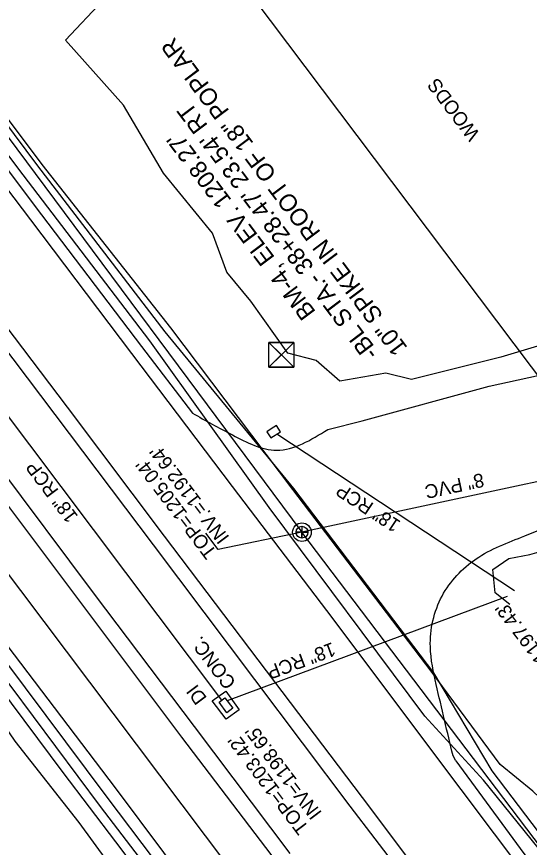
# Model space of a CAD drawing. Extents: x 1262092 to 1264624, y 774970 to 778314.
# Drawn here: x 1262454.7 to 1262603.1, y 777671.7 to 777912.2 of the extents above; entities that cross this region are included whole.
import ezdxf

# ---------------------------------------------------------------- set-up
doc = ezdxf.new("R2010")
doc.units = 0
for name, color, linetype in [('CTL Vertical Benchmark CELL', 7, 'Continuous'), ('Exist Horizontal Alignment', 7, 'Continuous'), ('Exist Right of Way Line', 7, 'Continuous'), ('Exist Roads EOP', 7, 'Continuous'), ('Exist Roads EOP Other', 7, 'Continuous'), ('Exist Roads EOT', 7, 'Continuous'), ('Exist Structure Minor Drop Inlet', 7, 'Continuous'), ('Exist Structure Minor Drop Inlet Text', 7, 'Continuous'), ('Exist Structure Minor Drop Inlet Top Elevation', 7, 'Continuous'), ('Exist Structure Minor Paved Ditch or Gutter', 7, 'Continuous'), ('Exist Structure Minor Paved Ditch or Gutter Text', 7, 'Continuous'), ('Exist Structure Minor Pipes RCP 18 Inch', 7, 'Continuous'), ('Exist Structure Minor Pipes RCP 18 Inch Invert', 7, 'Continuous'), ('Exist Structure Minor Pipes RCP 18 Inch Text', 7, 'Continuous'), ('Exist Utilities Gas UG Line SUE LOS B', 7, 'Continuous'), ('Exist Utilities Sanitary Sewer Manhole CELL', 7, 'Continuous'), ('Exist Utilities Sanitary Sewer Manhole Leader', 7, 'Continuous'), ('Exist Utilities Sanitary Sewer Manhole Text', 7, 'Continuous'), ('Exist Utilities Sanitary Sewer UG Line', 7, 'Continuous'), ('Exist Utilities Sanitary Sewer UG Line Text', 7, 'Continuous'), ('Exist Utilities Telephone UG FO SUE LOS B', 7, 'Continuous'), ('Exist Utilities Water UG Line SUE LOS B', 7, 'Continuous'), ('Exist Vegetation Woods Line Text', 7, 'Continuous'), ('Prop Conc 5in Monolithic Keyed In Island', 7, 'Continuous'), ('Prop Terminator CELL', 7, 'Continuous'), ('Typical Text Label CELL', 7, 'Continuous')]:
    doc.layers.add(name, color=color, linetype=linetype)

# ---------------------------------------------------------------- blocks, each defined once
blk = doc.blocks.new('CTL VERTICAL BENCHMARK')
at = {"layer": 'CTL Vertical Benchmark CELL'}
blk.add_line((0, 0), (0, 0), dxfattribs=at)
blk.add_lwpolyline([(-0.072, 0.07175), (0.07175, 0.07175), (0.07175, -0.072), (-0.072, -0.072)], close=True, dxfattribs=at)
for points in [[(0.07175, 0.07175), (-0.072, -0.072), (-0.000125, -0.000125), (0.07175, -0.072), (-0.072, 0.07175)], [(-0.000125, -0.000125), (0.07175, 0.07175), (-0.072, 0.07175), (-0.000125, -0.000125)], [(-0.000125, -0.000125), (-0.072, -0.072), (0.07175, -0.072), (-0.000125, -0.000125)]]:
    blk.add_lwpolyline(points, dxfattribs=at)
blk = doc.blocks.new('EXIST UTILITIES SANITARY SEWER MANHOLE')
at = {"layer": 'Exist Utilities Sanitary Sewer Manhole CELL'}
blk.add_lwpolyline([(0, 0.03425), (0, -0.03425), (0, 0), (0.03425, 0), (-0.03425, 0)], dxfattribs=at)
for radius in [0.05389, 0.03425]:
    blk.add_circle((0, 0), radius, dxfattribs=at)

msp = doc.modelspace()

# ---------------------------------------------------------------- linework, layer by layer
at = {"layer": 'Exist Horizontal Alignment'}
msp.add_line((1264460.35, 775084.79), (1262255.05, 778012.66), dxfattribs=at)
at = {"layer": 'Exist Right of Way Line'}
msp.add_line((1262380.46, 778107.12), (1263428.45, 776715.75), dxfattribs=at)
at = {"layer": 'Exist Roads EOP'}
for p, q in [((1262601.79, 777761.82), (1262629.33, 777772.97)), ((1262581.77, 777696.76), (1262581, 777698.2))]:
    msp.add_line(p, q, dxfattribs=at)
for points in [[(1262311.57, 778054.09), (1262320.31, 778042.27), (1262347.65, 778006.04), (1262376.01, 777968.97), (1262404.37, 777930.89), (1262432.91, 777893.24), (1262461.84, 777854.83), (1262490.86, 777816.65), (1262505.6, 777797.35)], [(1262285.77, 778035.09), (1262294.3, 778023.82), (1262322.73, 777986.32), (1262351.06, 777948.49), (1262379.86, 777910.83), (1262408.98, 777872.17), (1262437.51, 777834.34), (1262465.79, 777796.98), (1262494.21, 777759.25), (1262523.56, 777720.28), (1262551.17, 777683.56), (1262580.06, 777645.73)], [(1262533.86, 777669.85), (1262506.16, 777706.68), (1262477.25, 777744.96), (1262448.83, 777782.76), (1262448.77, 777782.75), (1262419.94, 777820.99), (1262391.44, 777858.59), (1262362.67, 777897.37), (1262333.74, 777935.31), (1262305.02, 777973.3), (1262276.84, 778010.82), (1262268.09, 778022.33)], [(1262508.59, 777649.5), (1262480.62, 777686.61), (1262451.55, 777725.45), (1262423.03, 777763.23), (1262394.37, 777801.14), (1262366.02, 777838.6), (1262337.3, 777876.52), (1262308.59, 777914.31), (1262279.57, 777952.95), (1262251.16, 777991.02), (1262242.02, 778002.99)], [(1262581.77, 777696.76), (1262605.02, 777665.12), (1262633.36, 777627.24), (1262661.91, 777589.34), (1262690.46, 777551.49), (1262719.22, 777513.4), (1262746.97, 777476.08), (1262773.62, 777440.76), (1262802.75, 777402.21), (1262831.32, 777364.09), (1262858.19, 777328.14), (1262886.09, 777290.94), (1262913.38, 777255.47), (1262941.92, 777217.23), (1262974.58, 777174.56)]]:
    msp.add_lwpolyline(points, dxfattribs=at)
for points in [[(1262505.6, 777797.35), (1262517.14, 777791.06), (1262529.95, 777786.65), (1262544.75, 777792.63)], [(1262581, 777698.2), (1262576.15, 777718.84), (1262574.44, 777729.73), (1262577.84, 777744.43), (1262587.67, 777755.18), (1262601.79, 777761.82)]]:
    msp.add_spline(points, degree=3, dxfattribs=at)
at = {"layer": 'Exist Roads EOP Other'}
msp.add_lwpolyline([(1262544.75, 777792.63), (1262554.66, 777795.19), (1262591.5, 777805.2), (1262611.36, 777809.52), (1262633.47, 777814.22), (1262657.91, 777819.26), (1262661.57, 777820.89), (1262663.59, 777822.69), (1262664.84, 777824.45), (1262667.34, 777828.67), (1262677.77, 777830.58)], dxfattribs=at)
at = {"layer": 'Exist Roads EOT'}
for points in [[(1262308.34, 778051.79), (1262317.32, 778039.93), (1262344.37, 778004.19), (1262372.89, 777966.62), (1262401.21, 777929.2), (1262429.93, 777891.21), (1262458.73, 777853.38), (1262487.94, 777814.62), (1262517.12, 777776.18), (1262546.22, 777737.8), (1262573.92, 777700.82), (1262602.3, 777663.12)], [(1262289.2, 778037.57), (1262297.52, 778026.31), (1262325.76, 777988.99), (1262354.59, 777951.12), (1262382.95, 777913.24), (1262412.22, 777874.41), (1262440.97, 777836.5), (1262469.27, 777799.15), (1262497.42, 777761.79), (1262526.95, 777722.8), (1262554.72, 777686.15), (1262583.3, 777648.11)], [(1262530.21, 777667.14), (1262502.53, 777703.54), (1262473.57, 777742.17), (1262445.07, 777779.99), (1262416.17, 777818.02), (1262387.95, 777855.59), (1262358.59, 777894.64), (1262330.16, 777932.09), (1262301.01, 777970.53), (1262273.04, 778007.62), (1262264.28, 778019.28)], [(1262511.28, 777651.42), (1262483.32, 777688.89), (1262454.05, 777727.36), (1262425.45, 777765.13), (1262396.78, 777803.08), (1262368.42, 777840.5), (1262339.71, 777878.55), (1262311.54, 777915.71), (1262282.01, 777954.91), (1262253.58, 777992.51), (1262244.27, 778004.78)]]:
    msp.add_lwpolyline(points, dxfattribs=at)
at = {"layer": 'Exist Structure Minor Drop Inlet'}
msp.add_lwpolyline([(1262529.87, 777793.77), (1262528.4, 777792.85), (1262527.1, 777792.02), (1262528.25, 777790.2), (1262531.02, 777791.95)], close=True, dxfattribs=at)
msp.add_lwpolyline([(1262514.97, 777714.99), (1262517.24, 777711.96), (1262515.53, 777710.65), (1262513.32, 777713.68), (1262514.97, 777714.99)], dxfattribs=at)
at = {"layer": 'Exist Structure Minor Paved Ditch or Gutter'}
msp.add_lwpolyline([(1262511.3, 777714.1), (1262515.24, 777716.92), (1262519.07, 777711.51), (1262515.32, 777708.77), (1262511.3, 777714.1)], dxfattribs=at)
at = {"layer": 'Exist Structure Minor Pipes RCP 18 Inch'}
for p, q in [((1262514.1, 777714.3), (1262275, 778031.81)), ((1262529.98, 777791.39), (1262598.81, 777746.05)), ((1262596.69, 777744.27), (1262515.67, 777714.06))]:
    msp.add_line(p, q, dxfattribs=at)
at = {"layer": 'Exist Utilities Gas UG Line SUE LOS B'}
msp.add_lwpolyline([(1262994.39, 777166.73), (1262980.63, 777180.77), (1262951.12, 777219.34), (1262915.77, 777266.99), (1262883.3, 777310), (1262857.54, 777344.34), (1262828.14, 777381.91), (1262793.47, 777427.19), (1262760.54, 777472.85), (1262727.33, 777519.3), (1262694.08, 777555.83), (1262655.09, 777608.15), (1262623.1, 777653.3), (1262592.34, 777693.87), (1262575.48, 777722.21), (1262534.9, 777775.61), (1262497.72, 777820.92), (1262460.79, 777868.95), (1262430.33, 777909.82), (1262335.35, 778033.97), (1262366.66, 777994.16), (1262337.19, 778032.97), (1262314.26, 778062.88)], dxfattribs=at)
msp.add_lwpolyline([(1262994.39, 777166.73), (1262980.63, 777180.77), (1262951.12, 777219.34), (1262915.77, 777266.99), (1262883.3, 777310), (1262857.54, 777344.34), (1262828.14, 777381.91), (1262793.47, 777427.19), (1262760.54, 777472.85), (1262727.33, 777519.3), (1262694.08, 777555.83), (1262655.09, 777608.15), (1262623.1, 777653.3), (1262592.34, 777693.87), (1262575.48, 777722.21), (1262534.9, 777775.61), (1262497.72, 777820.92), (1262460.79, 777868.95), (1262430.33, 777909.82), (1262335.35, 778033.97), (1262366.66, 777994.16), (1262337.19, 778032.97), (1262314.26, 778062.88)], dxfattribs=at)
at = {"layer": 'Exist Utilities Sanitary Sewer Manhole Leader'}
msp.add_lwpolyline([(1262537.27, 777762.91), (1262513.03, 777757.87), (1262509.43, 777762.66)], dxfattribs=at)
at = {"layer": 'Exist Utilities Sanitary Sewer UG Line'}
for p in [(1262150.97, 778282.31), (1263142.14, 776964.69)]:
    msp.add_line(p, (1262537.27, 777762.91), dxfattribs=at)
msp.add_lwpolyline([(1262668.77, 777791.06), (1262537.27, 777762.91)], dxfattribs=at)
at = {"layer": 'Exist Utilities Telephone UG FO SUE LOS B'}
for points in [[(1262989.94, 777168.07), (1262951.99, 777219.94), (1262916.42, 777267.81), (1262888.77, 777316.31), (1262864.92, 777351.47), (1262838.91, 777387.68), (1262799.61, 777432.02), (1262765.27, 777476.73), (1262731.32, 777522.28), (1262700.44, 777560.94), (1262661.97, 777612.3), (1262627.92, 777657.64), (1262612.11, 777680.33), (1262604.08, 777687.9), (1262594.67, 777695.7), (1262574.71, 777722.66), (1262534.65, 777775.25), (1262499.34, 777822.06), (1262462.07, 777869.42), (1262431.13, 777910.63), (1262336.58, 778034.92), (1262368.35, 777994.88), (1262338.32, 778033.37), (1262315.72, 778063.86)], [(1262989.94, 777168.07), (1262951.99, 777219.94), (1262916.42, 777267.81), (1262888.77, 777316.31), (1262864.92, 777351.47), (1262838.91, 777387.68), (1262799.61, 777432.02), (1262765.27, 777476.73), (1262731.32, 777522.28), (1262700.44, 777560.94), (1262661.97, 777612.3), (1262627.92, 777657.64), (1262612.11, 777680.33), (1262604.08, 777687.9), (1262594.67, 777695.7), (1262574.71, 777722.66), (1262534.65, 777775.25), (1262499.34, 777822.06), (1262462.07, 777869.42), (1262431.13, 777910.63), (1262336.58, 778034.92), (1262368.35, 777994.88), (1262338.32, 778033.37), (1262315.72, 778063.86)], [(1262982.78, 777167.11), (1262946.46, 777216.4), (1262911.63, 777263.89), (1262904.55, 777273.66), (1262904.75, 777279.08), (1262882.68, 777309.56), (1262855.72, 777342.59), (1262826.17, 777380.64), (1262792.14, 777426.47), (1262758.72, 777471.04), (1262724.36, 777517.1), (1262692.7, 777554.83), (1262654.13, 777607.32), (1262621.89, 777651.43), (1262589.79, 777691.14), (1262572.86, 777709.66), (1262527.82, 777770.05), (1262493.25, 777818.33), (1262456.6, 777866.38), (1262426.24, 777906.46), (1262391.81, 777952.18), (1262362.73, 777991.03), (1262332.92, 778030.12), (1262309.95, 778059.98)], [(1262497.69, 777644.72), (1262472.81, 777678.82), (1262454.22, 777702.45), (1262410.39, 777767.02), (1262381.85, 777803.45), (1262346.33, 777843.25), (1262319.52, 777872.83), (1262288.46, 777910.54), (1262263.91, 777943.64), (1262260.24, 777952.77), (1262251.56, 777965.81), (1262224.91, 778006.43)]]:
    msp.add_lwpolyline(points, dxfattribs=at)
at = {"layer": 'Exist Utilities Water UG Line SUE LOS B'}
msp.add_lwpolyline([(1262961.53, 777041.32), (1262916.91, 777099.45), (1262892.75, 777131.3), (1262862.6, 777171.1), (1262817.98, 777226.85), (1262789.55, 777268.74), (1262774.27, 777287.66), (1262763.83, 777305.05), (1262732.33, 777346.94), (1262685.88, 777410.11), (1262660.87, 777443.18), (1262632.31, 777481.08), (1262598.3, 777526.4), (1262560.14, 777576.52), (1262506.51, 777647.45), (1262479.01, 777683.48), (1262453.07, 777718.25), (1262416.94, 777766.02), (1262382.77, 777811.78), (1262358.61, 777844.73), (1262327.38, 777885.68), (1262302.32, 777918.54), (1262259.45, 777971.43), (1262223.66, 778020.3)], dxfattribs=at)
at = {"layer": 'Prop Conc 5in Monolithic Keyed In Island'}
for points in [[(1262533.14, 777814.74), (1262522.5, 777829.79), (1262515.5, 777838.16), (1262511.37, 777849.45), (1262497.15, 777866.82), (1262485.63, 777886.53), (1262468.79, 777905.4), (1262479.72, 777917.06), (1262479.8, 777939.53), (1262486.53, 777963.05), (1262485.45, 777968.26)], [(1262669.52, 777841.52), (1262663.48, 777834.07), (1262654.46, 777829.52), (1262625.06, 777822.67), (1262594.86, 777813.61), (1262568.96, 777807.09), (1262561.51, 777808.92), (1262548.24, 777806.67), (1262541.36, 777812.67), (1262533.14, 777814.74)], [(1262597.47, 777741.98), (1262593.25, 777745.35), (1262592.49, 777752.09), (1262597.12, 777755.26), (1262603.2, 777756.41), (1262615.39, 777759.97), (1262624.68, 777755.85), (1262626.75, 777749.85), (1262631.1, 777744.24), (1262642.14, 777734.31), (1262649.45, 777730.68), (1262655.3, 777732.37), (1262661.91, 777740.44), (1262669.23, 777746.99), (1262676.7, 777747.14), (1262684.82, 777742.44), (1262695.74, 777744.15), (1262709.96, 777741.06), (1262732.77, 777726.31), (1262741.03, 777722.96), (1262742.69, 777718.79), (1262747.97, 777708.45), (1262760.99, 777691.69), (1262778.66, 777667.76)]]:
    msp.add_lwpolyline(points, dxfattribs=at)
at = {"layer": 'Typical Text Label CELL'}
msp.add_lwpolyline([(1262768.2, 777292.26), (1262757.43, 777308.58), (1262750.97, 777317.87), (1262727.73, 777348.88), (1262712, 777369.55), (1262697.36, 777389.13), (1262675.04, 777418.88), (1262656.25, 777443.92), (1262630.05, 777478.82), (1262611.34, 777503.87), (1262588.61, 777533.8), (1262569.91, 777558.5), (1262554.82, 777578.68), (1262539.79, 777598.72), (1262516.99, 777628.51), (1262502.14, 777648.38), (1262483.36, 777673.29), (1262468.18, 777693.3), (1262449.46, 777718.32)], dxfattribs=at)

# ---------------------------------------------------------------- block references
at = {"layer": 'CTL Vertical Benchmark CELL', "xscale": 50, "yscale": 50}
msp.add_blockref('CTL VERTICAL BENCHMARK', (1262531.33, 777814.27), dxfattribs=at)
msp.add_blockref('CTL VERTICAL BENCHMARK', (1262531.33, 777814.27), dxfattribs=at)
msp.add_blockref('CTL VERTICAL BENCHMARK', (1262531.33, 777814.27), dxfattribs=at)
at = {"layer": 'Exist Utilities Sanitary Sewer Manhole CELL', "xscale": 50, "yscale": 50}
msp.add_blockref('EXIST UTILITIES SANITARY SEWER MANHOLE', (1262537.27, 777762.91), dxfattribs=at)
msp.add_blockref('EXIST UTILITIES SANITARY SEWER MANHOLE', (1262537.27, 777762.91), dxfattribs=at)

# ---------------------------------------------------------------- texts
at = {"layer": 'Exist Structure Minor Drop Inlet Text'}
msp.add_text('DI', height=4, rotation=126.9874, dxfattribs=at).set_placement((1262509.93, 777714.91))
at = {"layer": 'Exist Structure Minor Drop Inlet Top Elevation'}
msp.add_text("TOP=1203.42'", height=4, rotation=126.9874, dxfattribs=at).set_placement((1262539.48, 777677.32))
at = {"layer": 'Exist Structure Minor Paved Ditch or Gutter Text'}
msp.add_text('CONC.', height=4, rotation=126.9187, dxfattribs=at).set_placement((1262518.38, 777719.36))
at = {"layer": 'Exist Structure Minor Pipes RCP 18 Inch Invert'}
for s, p in [("INV=1197.43'", (1262615.6, 777717.25)), ("INV=1198.65'", (1262543.22, 777681.65))]:
    msp.add_text(s, height=4, rotation=126.9874, dxfattribs=at).set_placement(p)
at = {"layer": 'Exist Structure Minor Pipes RCP 18 Inch Text'}
for rotation, p in [(126.9805, (1262472.64, 777767.52)), (146.6252, (1262566.1, 777765.92)), (200.447, (1262546.05, 777731.14))]:
    msp.add_text('18" RCP', height=4, rotation=rotation, dxfattribs=at).set_placement(p)
at = {"layer": 'Exist Utilities Sanitary Sewer Manhole Text'}
for s, rotation, p in [("INV.=1192.64'", 126.9874, (1262516.44, 777761.44)), ("TOP=1205.04'", 126.9746, (1262512.78, 777757.14))]:
    msp.add_text(s, height=4, rotation=rotation, dxfattribs=at).set_placement(p)
at = {"layer": 'Exist Utilities Sanitary Sewer UG Line Text'}
msp.add_text('8" PVC', height=4, rotation=192.0819, dxfattribs=at).set_placement((1262589.49, 777780.06))
at = {"layer": 'Exist Vegetation Woods Line Text'}
msp.add_text('WOODS', height=4, rotation=126.9874, dxfattribs=at).set_placement((1262588.98, 777878.14))
at = {"layer": 'Prop Terminator CELL'}
for s, p in [('10" SPIKE IN ROOT OF 18" POPLAR', (1262568.01, 777816.36)), ("-BL STA.- 38+28.47' 23.54' RT", (1262559.7, 777814.93)), ("BM-4, ELEV. 1208.27'", (1262541.44, 777826.71))]:
    msp.add_text(s, height=5, rotation=126.9874, dxfattribs=at).set_placement(p)

doc.saveas('drawing.dxf')
